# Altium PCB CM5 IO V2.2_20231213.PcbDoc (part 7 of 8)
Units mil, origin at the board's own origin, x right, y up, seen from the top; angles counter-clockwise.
Board outline 6299.61 x 3544.09 mil, 4 copper layers (Top, GND, Power, Bottom), stack 35.4 mil thick; 482 components, 404 nets, 1857 pads, 2731 vias.
Unrouted connection lines stored in the file: 1872.
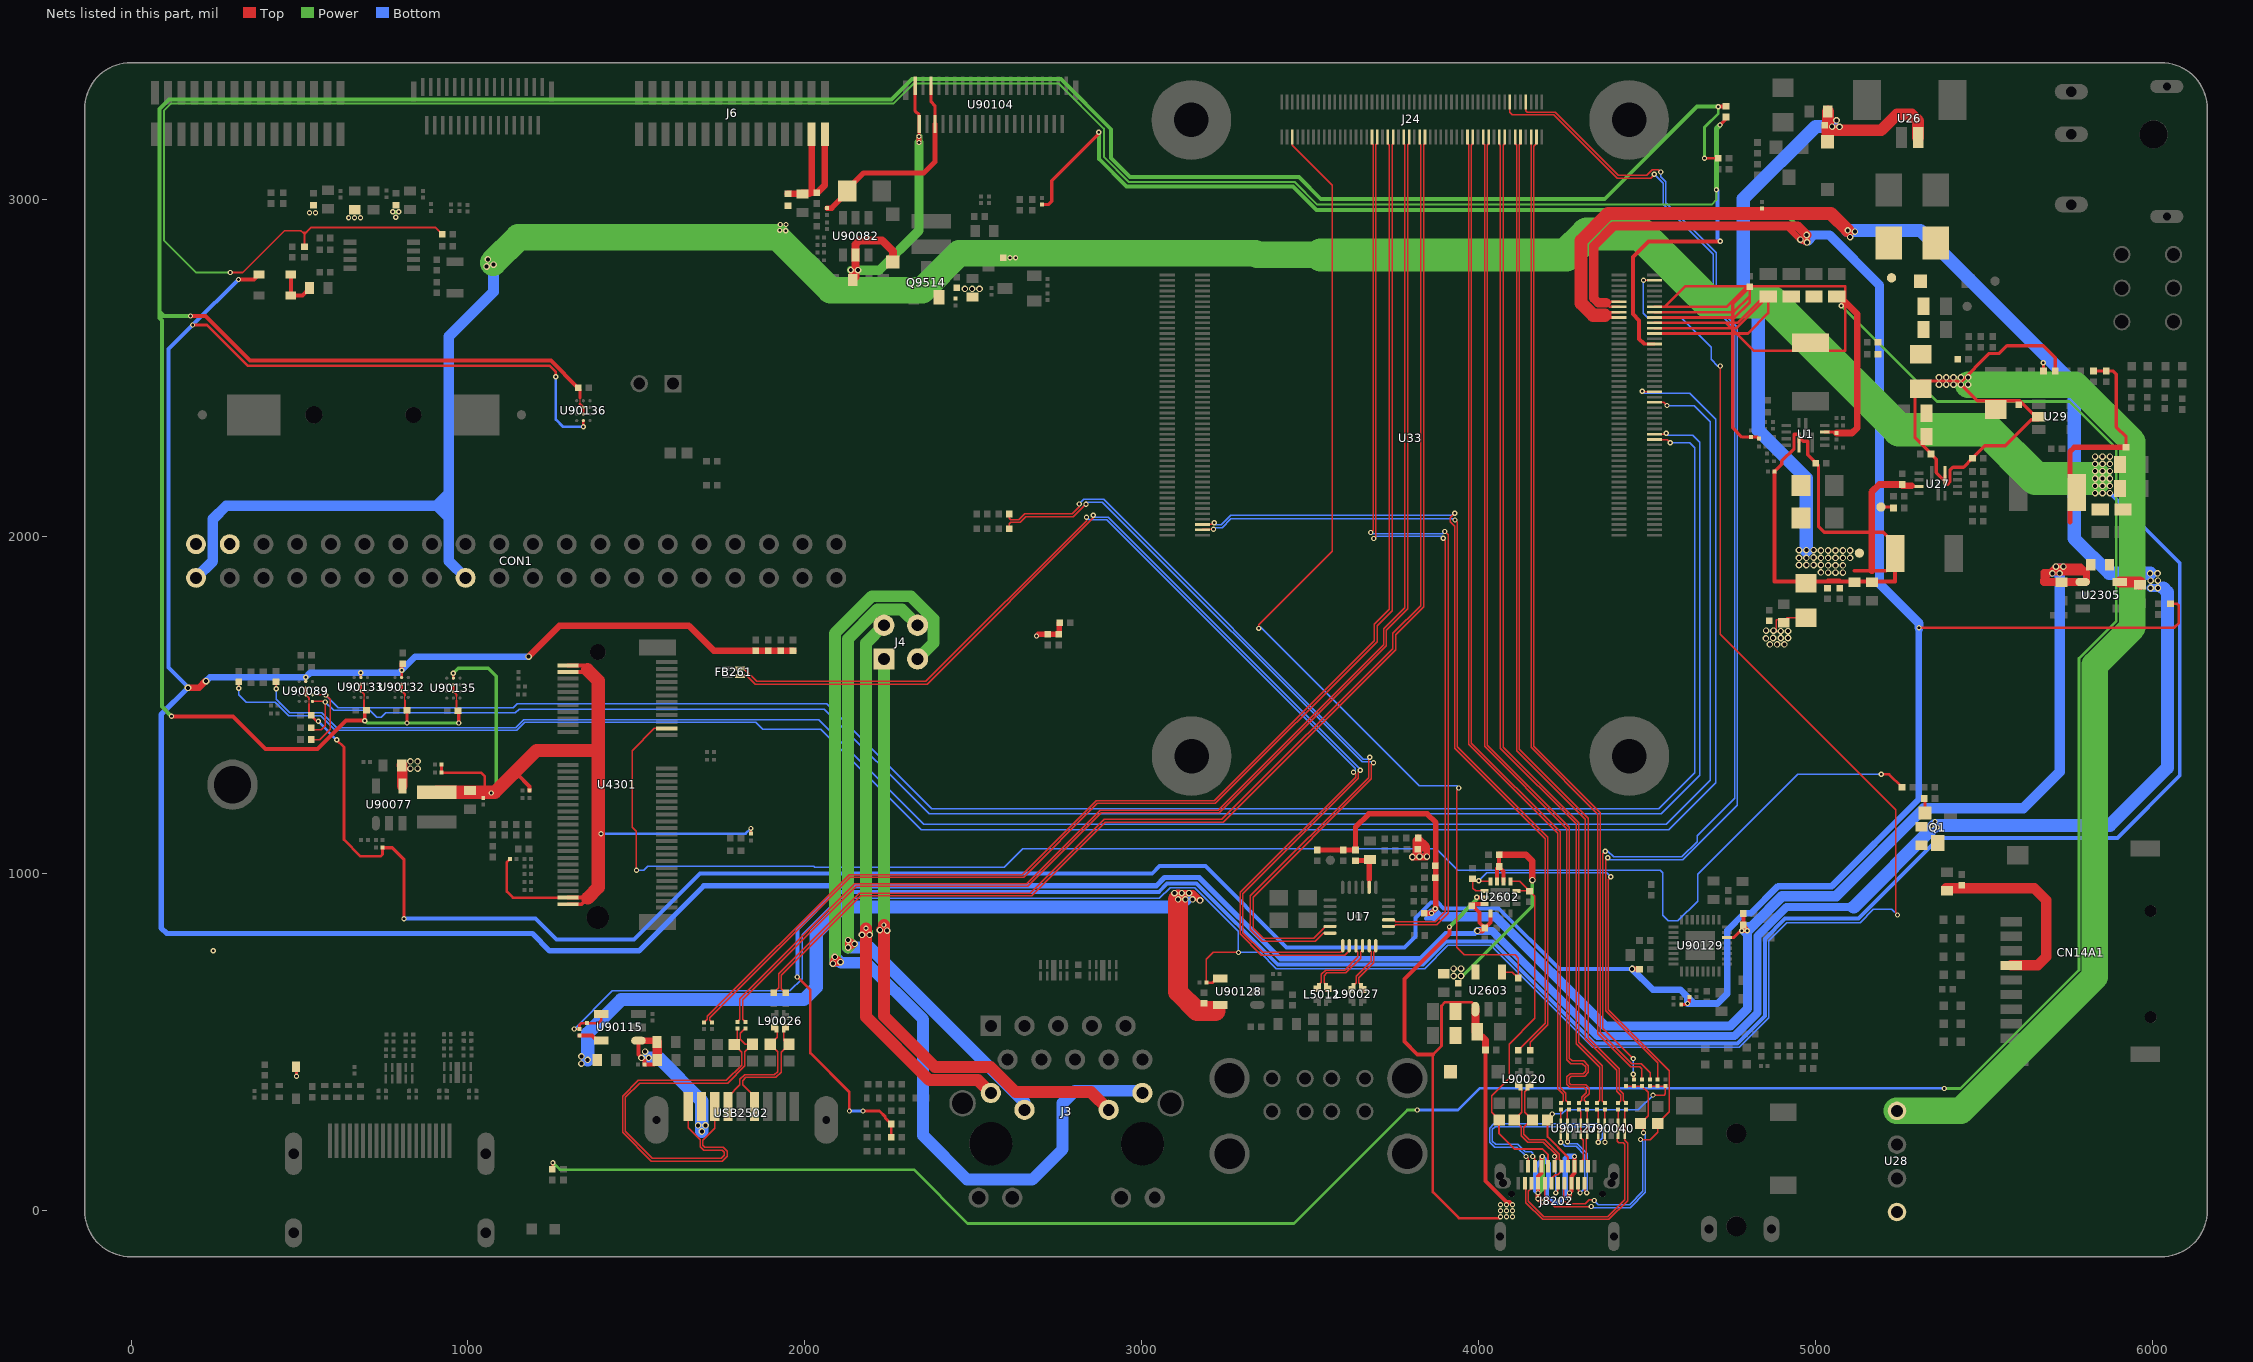
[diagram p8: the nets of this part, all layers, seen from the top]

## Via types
v1: diameter 15.75, hole 7.87, Top to Bottom, 2292 vias
v2: diameter 19.68, hole 11.81, Top to Bottom, 439 vias

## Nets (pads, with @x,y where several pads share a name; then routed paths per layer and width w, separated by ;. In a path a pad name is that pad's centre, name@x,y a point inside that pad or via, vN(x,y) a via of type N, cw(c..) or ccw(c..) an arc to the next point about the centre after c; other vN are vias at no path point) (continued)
SSTX_1N: C2280.2 D90035.1 USB2502.8 | length 1196.5
  Top w3.94: USB2502.8@1732.35,307.18 1732.35,243.11 1696.85,207.61 1696.85,191.93 1702.76,186.02 1757.87,186.02 1768.7,175.2 1768.7,159.45 1754.92,145.67 1544.23,145.67 1458.66,231.24 1458.66,337.66 1505.85,384.84 1766.99,384.84 1812.91,430.76 1812.91,468.98 D90035.1@1790.35,491.54 1790.35,496.06 1799.21,504.92 C2280.2@1799.21,539.37
SSTX_1P: C2281.2 D90037.1 USB2502.9 | length 1200.7
  Top w3.94: USB2502.9@1653.61,307.18 1653.61,244.03 1688.98,208.66 1688.98,188.67 1699.49,178.15 1754.61,178.15 1760.83,171.94 1760.83,162.71 1751.66,153.54 1547.49,153.54 1466.54,234.5 1466.54,334.39 1509.11,376.97 1770.25,376.97 1821.85,428.57 1821.85,469.88 D90037.1@1844.49,492.52 1823.43,492.52 1808.07,507.87 1808.07,524.61 C2281.2@1822.83,539.37
TP_INT_L: R95596.1 U33.37 U90089.C3 | length 5564.3
  Top w3.94: R95596.1@534.45,1396.65 560.04,1396.65 590.55,1427.17 590.55,1515.75 v1(577.76,1528.54) 576.77,1529.53 U90089.C3@538.39,1529.53 ; U33.37@4520.47,2286.81 4558.66,2286.81 v1(4567.91,2277.56)
  Bottom w3.94: v1(577.76,1528.54) 615.16,1491.14 1133.86,1491.14 1145.67,1502.95 2064.96,1502.95 2375.98,1191.93 4533.46,1191.93 4639.76,1298.23 4639.76,2262.8 4625,2277.56 v1(4567.91,2277.56)
TP_RST_L: R95597.1 U33.39 U90089.D3 | length 5584.4
  Top w3.94: R95597.1@534.45,1432.09 534.45,1425.2 563.98,1425.2 576.77,1437.99 v1(576.77,1507.87) 576.77,1509.84 U90089.D3@538.39,1509.84 ; U33.39@4520.47,2302.56 4553.54,2302.56 v1(4556.1,2305.12)
  Bottom w3.94: v1(576.77,1507.87) 601.38,1483.27 708.66,1483.27 729.33,1462.6 743.11,1462.6 755.91,1475.39 1140.38,1475.39 1152.19,1487.2 2057.09,1487.2 2368.11,1176.18 4541.34,1176.18 4655.51,1290.35 4655.51,2279.53 4634.84,2300.2 4561.02,2300.2 v1(4556.1,2305.12)
TR0: J3.11 J4.2 | length 1785.8
  Top w19.68: v2(2169.29,816.93) v1(2181.1,836.61) v2(2191.93,816.93) v2(2169.29,816.93)
  Top w35.43: v1(2181.1,836.61) 2181.1,573.82 2369.09,385.83 2513.36,385.83 J3.11@2551.39,347.8
  Power w19.68: v2(2169.29,816.93) v2(2191.93,816.93) 2191.93,825.79 v1(2181.1,836.61) v2(2169.29,816.93)
  Power w35.43: v1(2181.1,836.61) 2181.1,849.38 ; 2181.13,849.41 2181.13,1682.66 J4.2@2234.28,1735.81
TR1: J3.12 J4.1 | length 2078.4
  Top w19.68: v2(2127.95,779.53) v2(2147.64,790.35) v2(2127.95,801.18) v2(2127.95,779.53)
  Power w19.68: v2(2127.95,779.53) 2134.22,776.93 v2(2147.64,790.35) 2127.95,810.04 v2(2127.95,801.18)
  Power w35.43: v2(2127.95,779.53) v2(2127.95,801.18) ; v2@2127.95,810.04 2127.95,1695.46 2214.97,1782.48 2287.61,1782.48 J4.1@2334.28,1735.81
  Bottom w19.68: v2(2127.95,779.53) v2(2127.95,801.18) v2(2147.64,790.35)
  Bottom w35.43: v2(2127.95,779.53) 2192.71,779.53 2651.39,320.84 J3.12@2651.39,297.8
TR2: J3.13 J4.4 | length 1942.8
  Top w19.68: v2(2222.44,830.71) 2222.44,834.65 v1(2234.25,846.46) v2(2244.09,829.72)
  Top w35.43: v1(2234.25,846.46) 2234.25,576.35 2385.4,425.2 2550.15,425.2 2624.96,350.39 2848.79,350.39 J3.13@2901.39,297.8
  Power w19.68: v2(2222.44,830.71) v1(2234.25,846.46) v2(2244.09,829.72) v2(2222.44,830.71)
  Power w35.43: v1(2234.25,846.46) J4.4@2234.28,1635.81
TR3: J3.14 J4.3 | length 3231.5
  Top w19.68: v2(2082.68,731.3) v2(2088.58,751.97) v2(2105.31,736.22) v2(2082.68,731.3)
  Power w19.68: v2(2082.68,731.3) 2082.68,751.97 v2(2088.58,751.97) v2(2105.31,736.22) v2(2082.68,731.3)
  Power w35.43: v2(2088.58,751.97) 2088.58,1711.77 2198.66,1821.85 2314.22,1821.85 2380.93,1755.13 2380.93,1682.46 J4.3@2334.28,1635.81
  Bottom w19.68: v2(2088.58,751.97) 2082.68,746.06 v2(2082.68,731.3) v2(2105.31,736.22)
  Bottom w35.43: v2(2088.58,751.97) 2106.3,734.25 2182.31,734.25 2350.39,566.16 2350.39,221.46 2481.3,90.55 2674.21,90.55 2764.76,181.1 2764.76,317.91 2801.18,354.33 2994.86,354.33 J3.14@3001.39,347.8
TYPEC0_CC1: C2612.1 ESD2702.1 J8202.A5 U2602.10 U2602.11 | length 1103.4
  Top w3.94: ESD2702.1@4060.04,267.32 4037.48,289.88 4037.48,339.65 4089.57,391.73 4089.57,492.07 4166.34,568.84 4166.34,931.48 4151.19,946.62 C2612.1@4150.22,946.62 ; U2602.11@4093.14,975.56 4121.29,975.56 C2612.1@4150.22,946.62 ; U2602.10@4111.25,947.61 4150.22,947.61 C2612.1@4150.22,946.62
  Top w5.91: ESD2702.1@4060.04,267.32 4060.04,227.36 4105.31,182.09 4187.55,182.09 4205.26,164.37 J8202.A5@4205.26,130.51
TYPEC0_CC2: C2613.1 ESD2701.1 J8202.B5 U2602.1 U2602.14 | length 1917.8
  Top w3.94: v1(3999.02,977.36) v1@3999.02,975.56 ; U2602.1@4015.97,947.61 3990.39,947.61 3982.28,955.71 3982.28,981.69 C2613.1@3980.93,983.04 3980.93,978.88 3984.25,975.56 v1@3999.02,975.56 ; U2602.14@4034.08,975.56 v1@3999.02,975.56 ; J8202.B5@4254.92,79.33 J8202.B5@4254.48,79.33 4250.98,75.84 4250.98,28.1 4260.38,18.7 4314.96,18.7 4326.77,30.51 4335.63,30.51 v1(4342.52,28.54) ; v1(4390.75,989.17) 4391.66,988.26 4383.86,980.45 4383.86,595.47 4564.96,414.37 4564.96,291.93 ESD2701.1@4530.51,257.48 4530.51,231.3 4508.86,209.65 v1(4479.33,209.65)
  Bottom w3.94: v1(3999.02,977.36) 4022.64,1000.98 4378.94,1000.98 v1(4390.75,989.17) ; v1(4342.52,28.54) 4354.33,16.73 4446.85,16.73 4486.22,56.1 4486.22,202.76 v1(4479.33,209.65)
TYPEC0_OTG_DM: R91188.1 U33.103 | length 2475.8
  Top w3.94: U33.103@3179.13,2019.09 3179.13,2020.3 v1(3212.38,2020.3) ; v1(3929.13,2048.23) 3936.02,2041.34 3936.02,1375 4204.92,1106.1 4204.92,550.2 4152.56,497.83 R91188.1@4152.56,474.41
  Bottom w3.94: v1(3212.38,2020.3) 3217.67,2025.59 3237.65,2025.59 3264.22,2052.17 3925.2,2052.17 v1(3929.13,2048.23)
TYPEC0_OTG_DP: R91189.1 U33.105 | length 2517.3
  Top w3.94: U33.105@3179.13,2034.84 3208.65,2034.84 3214.56,2040.75 v1(3214.56,2039.95) ; v1(3928.15,2067.91) 3915.35,2055.12 3915.35,2042.32 3928.15,2029.53 3928.15,1371.06 4197.05,1102.17 4197.05,554.33 R91189.1@4117.13,474.41
  Bottom w3.94: v1(3214.56,2039.95) 3220.45,2034.05 3234.97,2034.05 3262.93,2062.01 3922.24,2062.01 v1(3928.15,2067.91)
TYPEC0_SBU1: C2010.1 J24.3 | length 2959.2
  Top w3.94: J24.3@4170.67,3184.65 4170.67,3165.35 4162.8,3157.48 4162.8,1376.97 4360.24,1179.53 4360.24,527.56 4453.74,434.06 4481.3,434.06 4507.87,407.48 C2010.1@4507.87,387.8
TYPEC0_SBU1_DC: J24.8 R2004.1 | length 3668.1
  Top w3.94: J24.8@4139.17,3288.58 4139.17,3262.8 4143.11,3258.86 4226.38,3258.86 4413.39,3071.85 4498.03,3071.85 4513.78,3087.6 4532.48,3087.6 v1(4539.37,3080.71) ; v1(4381.89,1046.26) 4381.4,1046.75 4375.98,1041.34 4375.98,591.54 4530.51,437.01 R2004.1@4530.51,387.8
  Bottom w3.94: v1(4381.89,1046.26) 4382.38,1046.75 4388.78,1040.35 4605.43,1040.35 4766.73,1201.66 4766.73,2620.08 4703.74,2683.07 4703.74,2840.55 4555.12,2989.17 4555.12,3051.18 4539.37,3066.93 v1(4539.37,3080.71)
TYPEC0_SBU2: C2011.1 J24.5 | length 2949
  Top w3.94: J24.5@4154.92,3184.65 4154.92,1373.03 4352.36,1175.59 4352.36,523.62 4449.8,426.18 4477.36,426.18 4483.27,420.28 C2011.1@4483.27,387.8
TYPEC0_SBU2_DC: J24.14 R2007.1 | length 3685.5
  Top w3.94: J24.14@4091.93,3288.58 4091.93,3258.46 4099.41,3250.98 4222.44,3250.98 4410.43,3062.99 4509.84,3062.99 v1(4520.67,3073.82) ; v1(4375,1064.96) 4368.11,1058.07 4368.11,539.37 v1(4457.68,449.8) ; v1(4457.68,403.54) 4459.65,401.57 R2007.1@4459.65,387.8
  Bottom w3.94: v1(4375,1064.96) 4382.87,1064.96 4399.61,1048.23 4602.16,1048.23 4647.64,1093.7 4647.64,1111.65 4758.86,1222.87 4758.86,2616.14 4695.87,2679.13 4695.87,2836.61 4547.24,2985.24 4547.24,3047.24 v1(4520.67,3073.82) ; v1(4457.68,403.54) v1(4457.68,449.8)
TYPEC0_SSRX1N: J24.11 R2013.1 | length 2999.3
  Top w3.94: J24.11@4107.68,3184.65 4107.68,3165.35 4112.2,3160.83 4112.2,1363.19 4315.94,1159.45 4315.94,508.19 4408.46,415.67 4408.46,353.35 4420.28,341.54 4420.28,325.4 R2013.1@4412.79,317.91
TYPEC0_SSRX1P: J24.9 R2015.1 | length 3000
  Top w3.94: J24.9@4123.43,3184.65 4124.02,3184.65 4124.02,3165.35 4120.08,3161.42 4120.08,1367.13 4323.82,1163.39 4323.82,511.45 4416.34,418.93 4416.34,357.28 4428.15,345.47 4428.15,326.17 R2015.1@4436.41,317.91
TYPEC0_SSRX2N: J24.23 R2016.1 | length 3117.9
  Top w3.94: J24.23@4013.19,3184.65 4012.8,3184.65 4012.8,3165.35 4016.73,3161.42 4016.73,1376.38 4260.83,1132.28 4260.83,446.85 4272.64,435.04 4307.09,435.04 4316.93,425.2 4316.93,412.4 4310.04,405.51 4270.67,405.51 4260.83,395.67 4260.83,373.17 4269.83,364.17 4312.99,364.17 4318.9,358.27 4318.9,348.43 4305.12,334.65 4305.12,325.77 R2016.1@4297.25,317.9
TYPEC0_SSRX2P: J24.21 R2017.1 | length 3117.3
  Top w3.94: J24.21@4028.94,3184.65 4028.94,3164.37 4024.61,3160.04 4024.61,1380.31 4268.7,1136.22 4268.7,450.79 4276.57,442.91 4310.35,442.91 4324.8,428.46 4324.8,409.14 4313.3,397.64 4274.61,397.64 4268.7,391.73 4268.7,376.43 4273.09,372.05 4316.93,372.05 4326.77,362.2 4326.77,345.16 4312.99,331.38 4312.99,325.78 R2017.1@4320.87,317.9
TYPEC0_SSTX1N: C2013.1 J24.17 | length 2994.2
  Top w3.94: J24.17@4060.43,3184.65 4060.04,3184.65 4060.04,3164.37 4063.98,3160.43 4063.98,1370.47 4288.39,1146.06 4288.39,494.09 4358.27,424.21 4358.27,326.38 C2013.1@4349.79,317.91
TYPEC0_SSTX1P: C2014.1 J24.15 | length 2993.4
  Top w3.94: J24.15@4076.18,3184.65 4076.18,3164.37 4071.85,3160.04 4071.85,1374.41 4296.26,1150 4296.26,498.03 4366.14,428.15 4366.14,325.18 C2014.1@4373.42,317.91
TYPEC0_SSTX2N: C2019.1 J24.29 | length 2987.8
  Top w3.94: J24.29@3965.94,3184.65 3965.55,3184.65 3965.55,3165.35 3969.49,3161.42 3969.49,1382.28 4233.27,1118.5 4233.27,360.24 4250,343.5 4250,324.78 C2019.1@4243.12,317.9
TYPEC0_SSTX2P: C2020.1 J24.27 | length 2988.4
  Top w3.94: J24.27@3981.69,3184.65 3981.69,3164.37 3977.36,3160.04 3977.36,1386.22 4241.14,1122.44 4241.14,364.17 4257.87,347.44 4257.87,326.76 C2020.1@4266.74,317.9
TYPEC5V_PWREN_H: J24.95 R2611.1 U2603.4 | length 3178.5
  Top w3.94: v1(3346.46,1726.38) 3346.46,1737.2 3564.96,1955.71 3564.96,3042.04 3446.26,3160.74 J24.95@3446.26,3184.65 ; v1(3939.96,1252.95) 3933.8,1246.79 3933.8,780.57 3956.63,757.74 4107.33,757.74 4117.13,747.94 R2611.1@4117.13,688.98 4099.41,706.69 U2603.4@4067.91,706.69
  Bottom w3.94: v1(3346.46,1726.38) 3350.89,1730.81 3822.83,1258.86 3934.06,1258.86 v1(3939.96,1252.95)
TYPEC_SBU1: C2010.2 ESD2703.1 J8202.A8 R2004.2 R2005.1 | length 616.9
  Top w3.94: ESD2703.1@4203.74,267.32 4203.74,269.05 4202.01,269.05 4217.95,285 v1(4217.52,285.43) ; C2010.2@4507.87,368.11 R2004.2@4530.51,368.11 R2005.1@4553.15,368.11 4553.15,345.47 4549.21,341.54 v1(4516.73,341.54)
  Top w5.91: ESD2703.1@4203.74,267.32 4203.74,217.52 4264.32,156.94 J8202.A8@4264.32,130.51
  Bottom w3.94: v1(4217.52,285.43) 4246.06,285.43 4258.86,298.23 4473.43,298.23 v1(4516.73,341.54)
TYPEC_SBU2: C2011.2 ESD2704.1 J8202.B8 R2006.1 R2007.2 | length 760.7
  Top w3.94: J8202.B8@4195.42,79.33 4194.88,79.33 4194.88,40.35 4224.41,10.83 v1(4333.66,10.83) ; R2006.1@4437.01,368.11 R2007.2@4459.65,368.11 C2011.2@4483.27,368.11 4501.89,349.49 4501.89,280.04 ESD2704.1@4479.33,257.48 4488.19,257.48 v1(4488.19,229.33)
  Bottom w3.94: v1(4333.66,10.83) 4336.61,7.87 4449.13,7.87 4494.09,52.84 4494.09,223.43 v1(4488.19,229.33)
TYPEC_SSRX1N: J8202.B10 R2013.2 U90040.4 U90040.7 | length 675.2
  Top w3.94: J8202.B10@4156.05,79.33 4156.05,65.5 4146.65,56.1 4146.65,25.9 4192.24,-19.69 4381.89,-19.69 4433.07,31.5 4433.07,194.88 4428.15,199.8 4415.35,199.8 4410.43,204.72 4410.43,212.6 4412.78,214.95 U90040.4@4412.78,224.9 ; U90040.4@4412.78,218.12 U90040.4@4412.78,224.9 ; R2013.2@4412.79,298.22 4412.79,282.48 U90040.7@4412.78,259.34 U90040.4@4412.78,224.9
TYPEC_SSRX1P: J8202.B11 R2015.2 U90040.5 U90040.6 | length 679.3
  Top w3.94: J8202.B11@4136.36,79.33 4136.36,66.39 4138.78,63.98 4138.78,22.64 4188.98,-27.56 4385.83,-27.56 4440.94,27.56 4440.94,198.82 4432.47,207.29 U90040.5@4432.47,224.9 U90040.6@4432.47,259.34 4432.47,294.29 R2015.2@4436.41,298.22
TYPEC_SSRX2N: J8202.A10 R2016.2 U90127.4 U90127.7 | length 175.6
  Top w3.94: R2016.2@4297.25,298.21 4302.17,293.3 U90127.7@4302.17,259.33 U90127.4@4302.17,224.89 4302.17,215.55 4310.04,207.68 4310.04,151.57 4303.69,145.22 J8202.A10@4303.69,130.51
TYPEC_SSRX2P: J8202.A11 R2017.2 U90127.5 U90127.6 | length 172
  Top w3.94: R2017.2@4320.87,298.21 4321.86,297.23 U90127.6@4321.86,259.33 U90127.5@4321.86,224.89 4321.86,214.57 4317.91,210.62 4317.91,151.57 4323.37,146.12 J8202.A11@4323.37,130.51
TYPEC_SSTX1N: C2013.2 J8202.A3 U90040.1 U90040.10 | length 681.5
  Top w3.94: v1(4159.45,159.45) 4165.35,153.54 4165.35,130.51 J8202.A3@4165.89,130.51 ; C2013.2@4349.79,298.22 4353.73,294.29 U90040.10@4353.73,259.34 U90040.1@4353.73,224.9 4354.33,224.9 v1(4354.33,201.77)
  Bottom w3.94: v1(4159.45,159.45) 4159.45,168.4 4154.62,173.23 4137.12,173.23 4115.47,194.88 4050.2,194.88 4040.05,205.03 4040.05,239.85 4048.23,248.03 4352.36,248.03 4366.14,234.25 4366.14,213.58 v1(4354.33,201.77)
TYPEC_SSTX1P: C2014.2 J8202.A2 U90040.2 U90040.9 | length 687.7
  Top w3.94: v1(4139.76,159.45) 4145.67,153.54 4145.67,130.51 J8202.A2@4146.21,130.51 ; C2014.2@4373.42,298.22 4373.42,282.48 U90040.9@4373.42,259.34 U90040.2@4373.42,224.9 4374.02,224.9 v1(4374.02,201.77)
  Bottom w3.94: v1(4139.76,159.45) 4112.2,187.01 4046.26,187.01 4031.5,201.77 4031.5,243.11 4044.29,255.91 4356.3,255.91 4374.02,238.19 v1(4374.02,201.77)
TYPEC_SSTX2N: C2019.2 J8202.B3 U90127.1 U90127.10 | length 332.2
  Top w3.94: v1(4243.11,201.77) U90127.1@4243.12,224.89 U90127.10@4243.12,259.33 C2019.2@4243.12,298.21 ; J8202.B3@4293.85,79.33 4294.29,79.33 4294.29,57.09 v1(4300.2,51.18)
  Bottom w3.94: v1(4243.11,201.77) 4255.91,188.98 4288.39,188.98 4313.98,163.39 4313.98,64.96 v1(4300.2,51.18)
TYPEC_SSTX2P: C2020.2 J8202.B2 U90127.2 U90127.9 | length 318.8
  Top w3.94: v1(4262.8,202.76) U90127.2@4262.81,224.89 U90127.9@4262.81,259.33 4262.81,294.28 C2020.2@4266.74,298.21 ; J8202.B2@4313.53,79.33 4313.98,79.33 4313.98,57.09 v1(4319.88,51.18)
  Bottom w3.94: v1(4262.8,202.76) 4268.7,196.85 4292.32,196.85 4321.85,167.32 4321.85,53.15 v1(4319.88,51.18)
UART2_RX_M0: R168.2 U33.51 | length 5790.9
  Top w3.94: R168.2@430.12,1567.91 431.1,1567.91 v1(431.1,1547.24) ; U33.51@4520.47,2397.05 4548.82,2397.05 v1(4558.07,2387.8)
  Bottom w3.94: v1(431.1,1547.24) 431.1,1515.75 471.46,1475.39 566.62,1475.39 609.93,1432.09 1141.62,1432.09 1165.24,1455.71 2041.34,1455.71 2352.36,1144.68 4556.16,1144.68 4687.01,1275.53 4687.01,2339.57 4638.78,2387.8 v1(4558.07,2387.8)
UART2_TX_M0: R167.2 U33.55 | length 6033.8
  Top w3.94: v1(319.88,1549.21) R167.2@319.88,1567.91 ; v1(4484.25,2430.12) 4484.25,2428.54 U33.55@4520.47,2428.54
  Bottom w3.94: v1(319.88,1549.21) 319.88,1529.53 342.52,1506.89 428.15,1506.89 467.52,1467.52 563.36,1467.52 606.67,1424.21 1144.88,1424.21 1168.5,1447.83 1853.35,1447.83 1874.02,1427.17 2046.26,1427.17 2344.49,1128.94 4562.68,1128.94 4702.76,1269.01 4702.76,2347.44 4625.98,2424.21 4490.16,2424.21 v1(4484.25,2430.12)
USB1_DM: L90027.2 R249.2 U17.11 | length 156.9
  Top w3.94: R249.2@3622.39,654.78 3622.63,654.78 3622.63,654.53 3628.29,660.19 L90027.2@3628.29,663.64 3628.29,667.32 3635.83,674.86 3635.83,693.9 3680.12,738.19 3680.12,766.73 3674.4,772.45 U17.11@3674.4,784.74
USB1_DP: L90027.1 R250.2 U17.12 | length 156.5
  Top w3.94: R250.2@3655.85,654.78 3655.61,654.78 3655.61,654.53 3649.95,660.19 L90027.1@3649.95,663.64 3649.95,669.29 3643.7,675.54 3643.7,689.96 3687.99,734.25 3687.99,765.75 3694.09,771.84 U17.12@3694.09,784.74
USB2_DM: L5012.4 R253.1 U17.9 | length 215.5
  Top w3.94: R253.1@3519,656.68 3519.74,656.68 3519.74,655.94 3524.91,661.11 L5012.4@3524.91,663.57 3524.91,668.31 3532.48,675.88 3532.48,699.5 3545.58,712.6 3601.38,712.6 3640.75,751.97 3640.75,765.75 3635.03,771.46 U17.9@3635.03,784.74
USB2_DP: L5012.3 R254.1 U17.10 | length 215.4
  Top w3.94: R254.1@3552.47,656.68 3551.73,656.68 3551.73,655.94 3546.56,661.11 L5012.3@3546.56,663.57 3546.56,668.31 3540.35,674.51 3540.35,696.24 3548.84,704.72 3605.31,704.72 3648.62,748.03 3648.62,766.73 3654.72,772.83 U17.10@3654.72,784.74
USB3_DM: FB261.1 R95142.2 U17.7 | length 3357.2
  Top w3.94: FB261.1@1812.01,1585.63 1827.76,1585.63 1852.36,1561.02 2362.2,1561.02 2855.31,2054.13 v1(2855.31,2062.01) ; U17.7@3595.66,784.74 3595.66,769.87 3590.55,764.76 3358.27,764.76 3299.21,823.82 3299.21,938.98 3641.73,1281.5 3641.73,1299.21 v1(3647.64,1305.12)
  Top w7.87: R95142.2@1798.72,1585.14 1812.01,1585.14 FB261.1@1812.01,1585.63
  Bottom w3.94: v1(2855.31,2062.01) 2855.31,2056.1 2899.61,2056.1 3650.18,1305.53 v1(3647.64,1305.12)
USB3_DP: FB261.2 R95141.2 U17.8 | length 3377.4
  Top w3.94: FB261.2@1812.01,1607.28 1817.91,1607.28 1856.3,1568.9 2358.27,1568.9 2835.63,2046.26 v1(2835.63,2056.1) ; U17.8@3615.35,784.74 3615.35,769.98 3602.26,756.89 3354.33,756.89 3291.34,819.88 3291.34,942.91 3633.86,1285.43 3633.86,1293.31 v1(3627.95,1299.21)
  Top w7.87: R95141.2@1798.72,1607.78 1812.01,1607.78 FB261.2@1812.01,1607.28
  Bottom w3.94: v1(2835.63,2056.1) 2843.5,2048.23 2895.67,2048.23 3632.87,1311.02 3632.87,1299.21 v1(3627.95,1299.21)
USB4_DM: R95611.2 U17.5 | length 2342
  Top w3.94: R95611.2@2606.3,2022.64 2606.3,2037.4 2610.24,2041.34 2638.17,2041.34 2654.71,2057.87 2796.46,2057.87 v1(2833.86,2095.28) ; U17.5@3558.26,841.83 3546.06,841.83 3510.53,806.3 3360.35,806.3 3329.72,836.92 3329.72,929.18 3681.1,1280.56 3681.1,1322.05 v1(3687.01,1327.95)
  Bottom w3.94: v1(2833.86,2095.28) 2833.86,2101.18 2882.68,2101.18 3653.54,1330.31 3687.01,1330.31 v1(3687.01,1327.95)
USB4_DP: R95610.1 U17.6 | length 2354.2
  Top w3.94: R95610.1@2606.3,2065.94 2606.3,2053.15 2610.24,2049.21 2634.84,2049.21 2651.57,2065.94 2793.11,2065.94 2814.17,2087.01 v1(2814.17,2095.67) ; U17.6@3558.26,822.14 3537.89,822.14 3514.17,798.43 3357.09,798.43 3321.85,833.66 3321.85,932.44 3673.23,1283.82 3673.23,1341.73 v1(3675.98,1344.49)
  Bottom w3.94: v1(2814.17,2095.67) 2827.56,2109.06 2886.17,2109.06 3657.03,1338.19 3669.69,1338.19 v1(3675.98,1344.49)
USB20_HOST0_DM: J24.65 U17.14 | length 2739.4
  Top w3.94: v1(3679.13,2010.83) 3686.02,2017.72 3686.02,3161.42 3682.09,3165.35 3682.09,3184.65 J24.65@3682.48,3184.65 ; U17.14@3731.49,841.83 3747.05,841.83 3752.66,847.44 3874.71,847.44 3908.46,881.2 3908.46,2003.94 v1(3898.62,2013.78)
  Bottom w3.94: v1(3679.13,2010.83) 3676.18,2010.83 3676.18,2007.87 3892.72,2007.87 v1(3898.62,2013.78)
USB20_HOST0_DP: J24.63 U17.15 | length 2702.6
  Top w3.94: v1(3687.99,1993.11) 3693.9,1999.02 3693.9,3162.4 3698.23,3166.73 J24.63@3698.23,3184.65 ; U17.15@3731.49,861.51 3747.05,861.51 3753.25,855.31 3870.77,855.31 3900.59,885.14 3900.59,1987.2 v1(3893.7,1994.09)
  Bottom w3.94: v1(3687.99,1993.11) 3694.88,2000 3887.8,2000 v1(3893.7,1994.09)
USB20_HOST1_DM: J24.47 R95552.1 | length 3839.7
  Top w3.94: R95552.1@1907.48,644.68 1922.24,659.45 1922.24,701.77 2161.42,940.94 2669.25,940.94 2887.77,1159.47 3237.48,1159.47 3744.76,1666.75 3744.76,1711.3 3827.76,1794.29 3827.76,3162.4 3823.82,3166.34 3823.82,3184.65 J24.47@3824.21,3184.65
USB20_HOST1_DP: J24.45 R95551.1 | length 3838.3
  Top w3.94: R95551.1@1942.91,644.68 1930.12,657.48 1930.12,697.83 2165.35,933.07 2672.59,933.07 2891.09,1151.57 3240.72,1151.57 3752.64,1663.49 3752.64,1707.36 3835.63,1790.35 3835.63,3161.42 3839.96,3165.75 J24.45@3839.96,3184.65
USB30_2_SSRXN: J24.59 R91181.1 | length 3978.6
  Top w3.94: R91181.1@1700.79,557.09 1709.65,565.94 1709.65,574.8 2130.91,996.06 2645.24,996.06 2863.94,1214.77 3214.83,1214.77 3689.64,1689.58 3689.64,1738.86 3734.25,1783.46 3734.25,3160.43 3729.72,3164.96 J24.59@3729.72,3184.65
USB30_2_SSRXP: J24.57 R91182.1 | length 3977.6
  Top w3.94: R91182.1@1724.48,557.18 1717.52,564.13 1717.52,570.87 2134.84,988.19 2648.54,988.19 2867.24,1206.89 3218.09,1206.89 3697.52,1686.32 3697.52,1734.92 3742.13,1779.53 3742.13,3161.42 3746.06,3165.35 3746.06,3184.65 J24.57@3745.47,3184.65
USB30_2_SSTXN: C2280.1 J24.53 | length 3952
  Top w3.94: C2280.1@1799.21,559.06 1807.09,566.93 1807.09,627.95 2147.64,968.5 2657.71,968.5 2876.38,1187.17 3226.21,1187.17 3717.2,1678.17 3717.2,1725.08 3780.51,1788.39 3780.51,3161.42 3776.57,3165.35 3776.57,3184.65 J24.53@3776.97,3184.65
USB30_2_SSTXP: C2281.1 J24.51 | length 3951.4
  Top w3.94: C2281.1@1822.83,559.06 1814.96,566.93 1814.96,624.02 2151.57,960.63 2660.98,960.63 2879.63,1179.28 3229.46,1179.28 3725.08,1674.91 3725.08,1721.14 3788.39,1784.45 3788.39,3161.42 3792.72,3165.75 J24.51@3792.72,3184.65
USB_HOST_PWREN_H: R91375.2 R95555.1 R95579.1 U33.97 U90115.4 U90128.4 | length 7403.6
  Top w3.94: v1(1314.96,537.4) R91375.2@1330.71,537.4 ; R95555.1@3190.94,675.2 3190.94,744.09 3211.61,764.76 v1(3286.42,764.76) ; v1(4488.19,2759.84) 4520.47,2759.84 U33.97@4520.47,2759.25 ; v1(4716.54,2504.92) 4716.54,1708.66 5236.22,1188.98 5236.22,881.89 v1(5242.13,875.98)
  Top w7.87: R91375.2@1330.71,537.4 1330.71,549.21 1336.61,555.12 R95579.1@1353.35,555.12 1386.81,555.12 1395.67,563.98 U90115.4@1395.67,581.69 ; R95555.1@3190.94,675.2 3209.64,675.2 3214.57,680.12 3228.2,687.99 U90128.4@3232.28,687.99
  Bottom w3.94: v1(1314.96,537.4) 1428.15,650.59 1955.51,650.59 1992.13,687.21 1992.13,816.7 2100.62,925.2 3052.03,925.2 3083.52,956.69 3157.11,956.69 3286.42,827.39 v1(3286.42,764.76) 3350.42,764.76 3398.65,716.54 3839,716.54 3907.9,785.43 4035.35,785.43 4337.52,483.27 4772.16,483.27 4860.24,571.35 4860.24,799.86 4913.72,853.35 5130.88,853.35 5170.25,892.72 5225.39,892.72 v1(5242.13,875.98) ; v1(4488.19,2759.84) 4488.19,2661.42 4500.98,2648.62 4600.39,2648.62 4688.98,2560.04 4688.98,2524.61 4708.66,2504.92 v1(4716.54,2504.92)
USBC_D+: ESD2706.1 J8202.A6 J8202.B6 L90020.3 R95547.2 | length 479.4
  Top w3.94: R95547.2@4117.13,372.05 4117.86,372.05 4117.86,372.79 4123.03,367.62 L90020.3@4123.03,365.16 4127.12,361.07 4127.12,290.21 ESD2706.1@4104.57,267.65 4125,247.22 4125,221.46 4144.69,201.77 4190.94,201.77 4230.31,162.4 4230.31,151.43 4224.95,146.06 J8202.A6@4224.95,130.51 ; v1(4228.35,51.18) 4234.25,57.09 4234.25,79.33 J8202.B6@4234.79,79.33
  Bottom w3.94: v1(4224.41,159.45) 4228.35,155.51 v1(4228.35,51.18)
USBC_D-: ESD27052.1 J8202.A7 J8202.B7 L90020.4 R95546.2 | length 415.3
  Top w3.94: R95546.2@4151.57,372.05 4144.69,372.05 L90020.4@4144.69,365.16 4144.69,360.24 4136.15,351.7 4136.15,290.21 ESD27052.1@4158.7,267.65 4154.53,267.65 4132.87,246 4132.87,225.39 4148.62,209.65 4194.88,209.65 4238.19,166.34 4238.19,151.57 4244.63,145.13 J8202.A7@4244.63,130.51 4242.13,128.01 4242.13,114.17 4233.27,105.31 4226.38,105.31 4215.1,94.04 J8202.B7@4215.1,79.33
USBHP_1N: D90032.1 L90026.3 R95553.2 USB2502.2 | length 374.7
  Top w3.94: USB2502.2@1771.72,307.18 1771.72,336.71 1807.09,372.07 1807.09,387.8 1820.87,401.57 1909.37,401.57 1919.21,411.42 1919.21,469.96 D90032.1@1896.65,492.52 1917.32,513.19 1917.32,530.51 1915.35,532.48 L90026.3@1915.35,536.42 1915.35,543.31 R95553.2@1908.46,543.31
USBHP_1P: D90031.1 L90026.4 R95550.2 USB2502.3 | length 373.2
  Top w3.94: USB2502.3@1850.46,307.18 1850.46,336.71 1814.96,372.2 1814.96,383.86 1824.8,393.7 1913.39,393.7 1929.13,409.45 1929.13,468.9 D90031.1@1952.76,492.52 1948.43,492.52 1937.01,503.94 L90026.4@1937.01,536.42 1937.01,538.88 1942.18,544.05 1942.18,543.31 R95550.2@1942.91,543.31
VBUS5V0_TYPEC: C658.1 C2611.1 C90780.1 C90781.1 D41.2 J8202.A4 J8202.A9 J8202.B4 J8202.B9 U2602.2 U2603.1 | length 3047.7
  Top w7.87: U2603.1@3989.17,596.45 3989.17,606.3 3978.04,617.43 3899.91,617.43 3888.78,606.3 3888.78,487.2 3863.19,461.61 3863.19,54.13 3940.94,-23.62 4060.04,-23.62 v1(4063.98,-19.69)
  Top w11.81: 3863.19,461.61 3816.93,461.61 3778.54,500 3778.54,686.02 3912.4,819.88 v1(3912.4,840.55) ; v1(3993.11,928.15) 3993.34,927.92 U2602.2@4015.97,927.92 ; C2611.1@4019.69,475.39 4019.69,86.58 4081.66,24.61 4090.55,24.61 v1(4099.41,15.75) ; v1(4175.2,51.18) 4175.73,58.85 J8202.B9@4175.73,79.33 4175.73,100 4185.58,109.84 J8202.A4@4185.58,130.51 4185.58,157.03 v1(4187.99,159.45) ; v1(4268.7,51.18) 4274.16,56.64 J8202.B4@4274.16,79.33 4274.16,100 4284,109.84 J8202.A9@4284,130.51 4284,151.39 v1(4283.46,159.45)
  Top w15.75: v1(4175.2,51.18) v1(4175.2,33.46) v1(4189.96,23.62) ; v1(4268.7,33.46) v1(4268.7,51.18)
  Top w19.68: C90780.1@3995.08,529.53 4019.69,504.92 C2611.1@4019.69,475.39
  Top w23.62: U2603.1@3989.17,596.45 3989.17,529.53 C90780.1@3995.08,529.53
  Power w11.81: v1(3912.4,840.55) 3993.11,921.26 v1(3993.11,928.15)
  Power w15.75: v1(4175.2,51.18) 4187.99,63.98 v1(4187.99,159.45)
  Bottom w15.75: v1(4175.2,51.18) 4168.9,57.48 4168.9,129.92 4183.37,144.39 4187.99,149.03 v1(4187.99,159.45) 4191.99,152.5 4206.69,137.8 4206.69,74.8 4200.79,68.9 4200.79,39.77 4216.93,23.62 4239.76,23.62 4255.91,39.77 4255.91,152.56 4263.78,160.43 4282.48,160.43 v1(4283.46,159.45)
  other v1: 4081.69,-19.69 4099.41,-19.69 4063.98,-1.97 4081.69,-1.97 4099.41,-1.97 4063.98,15.75 4081.69,15.75
VCC3V3_SD: C4.1 C5.1 CN14A1.4 Q1.3 R220.2 | length 594.8
  Top w31.5: C4.1@5386.81,955.71 5647.64,955.71 5684.06,919.29 5684.06,751.97 5658.46,726.38 CN14A1.4@5579.5,726.38
VCC3V3_SYS: C148.1 C149.1 C150.1 C154.1 C155.1 C156.1 CON1.1 CON1.17 FB2.1 FB6.1 FB7.1 L13.2 R4.2 R10.2 R157.1 R95530.1 | length 14548.5
  Top w7.87: v1(1977.36,691.93) 2015.75,653.54 2015.75,466.09 2131.89,349.94 v1(2131.89,294.29) ; v1(2172.24,294.29) 2221.09,294.29 2238.19,277.19 2238.19,273.62 R10.2@2255.91,255.91 R4.2@2255.91,216.54
  Top w9.84: C148.1@5823.82,2490.16 R157.1@5861.22,2490.16 5882.87,2490.16 5891.73,2481.3 5891.73,2323.82 5920.28,2295.28 C150.1@5920.28,2263.78
  Top w15.75: 5753.94,2042.32 5753.94,2110.24 L13.2@5773.62,2129.92 5773.62,2158.46 5753.94,2178.15 5753.94,2250.98 5766.73,2263.78 C150.1@5920.28,2263.78
  Power w3.94: v2@1074.8,2812.01 1075.79,2811.02 v2(1075.79,2806.1)
  Power w11.81: v1@777.56,2962.6 v1(794.29,2962.6)
  Power w78.74: v2@1074.8,2812.01 1149.61,2886.81 1919.29,2886.81 2075.79,2730.31 2348.43,2730.31 2457.68,2839.57 3336.61,2839.57 3341.54,2834.65 3531.5,2834.65
  Power w98.43: 3531.5,2834.65 4258.86,2834.65 4320.87,2896.65 4480.31,2896.65 4681.1,2695.87 4867.13,2695.87 5247.05,2315.94 5506.89,2315.94 5651.57,2171.26 v2(5828.74,2171.26)
  Bottom w7.87: v1(2131.89,294.29) v1(2172.24,294.29)
  Bottom w11.81: v1(1977.36,691.93) 1977.36,834.62 2087.63,944.88 3050.23,944.88 3074.83,969.49 3162.4,969.49 3403.54,728.35 3834.11,728.35 3903.01,797.24 4040.24,797.24 4342.41,495.08 4767.26,495.08 4848.43,576.24 4848.43,804.76 4908.83,865.16 5125.98,865.16 5365.16,1104.33 5894.69,1104.33 6079.72,1289.37 6079.72,1920.28 v2(5872.05,2127.95)
  Bottom w31.5: CON1.1@192.94,1876.36 243.11,1926.53 243.11,2051.18 282.48,2090.55 905.51,2090.55 ; CON1.17@992.94,1876.36 942.91,1926.39 942.91,2055.45 ; v2(1075.79,2806.1) 1075.79,2725.39 942.91,2592.52 942.91,2127.95 ; 905.51,2090.55 907.81,2090.55 ; 905.51,2090.55 942.91,2127.95 ; 907.81,2090.55 942.91,2055.45 ; 907.81,2090.55 942.91,2090.55 ; 942.91,2055.45 942.91,2090.55 ; 942.91,2090.55 942.91,2127.95
  other v1: 2608.27,2826.77 2625,2826.77 1942.91,2906.5 1925.2,2907.48 1926.18,2925.2 1943.9,2925.2 785.43,2946.85 529.53,2959.65 547.24,2959.65 776.57,2962.6
  other v2: 5828.74,2127.95 5850.39,2127.95 5828.74,2149.61 5850.39,2149.61 5872.05,2149.61 5850.39,2171.26 5872.05,2171.26 5828.74,2192.91 5850.39,2192.91 5872.05,2192.91 5828.74,2214.57 5850.39,2214.57 5872.05,2214.57 5828.74,2236.22 5850.39,2236.22 5872.05,2236.22 1055.12,2800.2 1059.06,2821.85
VCC3V3_WF: C266.1 C267.1 C268.1 L5011.2 R95151.2 R95153.2 R95154.2 R95281.1 U4301.2 U4301.4 U4301.72 U4301.74 U90135.A2 | length 3074.9
  Top w3.94: 1386.81,1116.14 1394.69,1116.14 v1(1394.69,1117.13)
  Top w7.87: R95281.1@921.26,1321.85 C266.1@921.26,1298.23 1038.39,1298.23 1050.2,1286.42 1050.2,1240.28 ; U90135.A2@956.7,1578.74 v1(956.69,1593.5) ; R95154.2@1124.96,1042.31 1115.16,1032.51 1115.16,945.87 1133.51,927.52 U4301.72@1296.47,927.52 ; R95151.2@1839.57,1117.13 v1(1839.57,1132.87)
  Top w9.84: C267.1@1003.94,1240.28 1003.94,1245.08 C267.1@1005.91,1245.08 ; C268.1@1045.28,1223.43 1045.28,1235.36 1050.2,1240.28 ; v1@1066.81,1240.28 v1(1068.9,1238.19)
  Top w11.81: 1134.84,1295.28 1144.63,1295.28 1182.05,1257.86 R95153.2@1182.05,1246.05 ; U4301.74@1296.47,907.83 1336.97,907.83 1355.31,926.18 1355.31,927.52 U4301.72@1296.47,927.52 ; U4301.4@1296.47,1596.81 1347.79,1596.81 1354.33,1603.35 1354.33,1616.5 U4301.2@1296.47,1616.5
  Top w39.37: L5011.2@907.48,1240.28 1003.94,1240.28 1050.2,1240.28 1066.81,1240.28 1079.85,1240.28 1134.84,1295.28 1203.74,1364.17 1386.81,1364.17 ; 1354.33,1603.35 1386.81,1570.87 1386.81,1364.17 ; 1355.31,926.18 1386.81,957.68 1386.81,1116.14 1386.81,1364.17
  Power w9.84: v1(956.69,1593.5) 971.46,1608.27 1060.04,1608.27 1083.66,1584.65 1083.66,1252.95 v1(1068.9,1238.19)
  Bottom w7.87: v1(1394.69,1117.13) 1823.82,1117.13 v1(1839.57,1132.87)
VCC5V0_SYS: C126.2 C127.2 C135.1 C136.1 C137.1 C138.1 C139.1 C265.1 C558.1 C559.1 C2606.1 C2607.1 C2608.1 C2609.1 C90480.1 C90483.1 C90484.1 C90789.1 C90790.1 CON1.2 CON1.4 D1.1 D37.2 L12.2 Q9514.2 R148.2 R316.1 R95041.1 R95122.2 R95616.2 TP10.1 U1.1 U26.2 U27.5 U28.4 U2602.12 U2602.13 U2603.5 U90077.4 | length 4884.2
  Top w7.87: D1.1@490.16,425.2 491.14,425.2 v1(491.14,397.64)
  Top w9.84: R95122.2@4876.97,2191.93 4898.62,2213.58 4898.62,2223.43 4935.04,2259.84 4935.04,2302.17 4947.82,2302.17 4949.8,2300.19 U1.1@4949.8,2277.56 4949.8,2293.58 4961.88,2281.5 4975.4,2281.5 4975.4,2242.13 5007.87,2209.65 5007.87,2028.54 5024.61,2011.81 5199.8,2011.81 5235.24,1976.38 L12.2@5235.24,1948.82 5235.24,1923.23 5209.65,1897.64 5166.34,1897.64 5114.17,1897.64 ; 5034.45,1870.08 5070.87,1870.08 ; 5283.46,2149.61 5285.43,2147.64 U27.5@5306.1,2147.64
  Top w11.81: U2602.13@4053.77,975.56 4053.77,1013.41 C2609.1@4060.04,1019.68 ; C2608.1@4060.04,1055.12 C2609.1@4060.04,1019.68 ; U2602.12@4073.45,975.56 4073.45,1005.67 4060.04,1019.08 C2609.1@4060.04,1019.68 ; R95122.2@4876.97,2191.93 4876.97,1866.14 5235.24,1866.14 L12.2@5235.24,1948.82
  Top w15.75: v1(2687.01,1703.74) 2691.93,1708.66 C90790.1@2720.47,1708.66 C90789.1@2752.95,1708.66 2754.43,1708.66 2754.43,1743.11 R95616.2@2755.91,1743.11
  Top w19.68: C2608.1@4060.04,1055.12 4138.78,1055.12 4158.46,1035.43 v2(4158.46,979.33) ; 5166.34,1897.64 5165.35,1898.62 5165.35,2130.91 5187.99,2153.54 C139.1@5255.91,2153.54 5255.91,2149.61 5283.46,2149.61
  Top w31.5: C265.1@803.11,1319.87 805.08,1319.87 U90077.4@805.08,1258.85
  Top w35.43: D37.2@5034.45,3170.28 5034.45,3204.72 ; C127.2@5035.43,3259.84 5035.43,3218.5 5034.45,3217.52 5034.45,3204.72 ; U26.2@5303.15,3183.07 5303.15,3232.28 5284.45,3250.98 5240.16,3250.98 5193.9,3204.72 5034.45,3204.72
  Power w9.84: v2(3946.85,694.88) 3950.83,694.88 4158.46,902.52 v2(4158.46,979.33)
  Bottom w39.37: v2(4971.46,1958.66) 4971.46,2171.75 4828.74,2314.47 4828.74,2674.47 4784.45,2718.76 4784.45,3001.23 4998.76,3215.55 v2(5048.23,3215.55)
  other v1: 244.09,769.68 645.67,2944.88 663.39,2944.88 681.1,2944.88
  other v2: 3925.2,694.88 3925.2,716.54 3946.85,716.54 828.74,1310.04 850.39,1310.04 828.74,1331.69 850.39,1331.69 5036.42,1891.73 5058.07,1891.73 5079.72,1891.73 5014.76,1892.72 5036.42,1913.39 5058.07,1913.39 5079.72,1913.39 4949.8,1914.37 4971.46,1914.37 4993.11,1914.37 5014.76,1914.37 4949.8,1936.02 4971.46,1936.02 5014.76,1936.02 5036.42,1936.02 5058.07,1936.02 5079.72,1936.02 5101.38,1936.02 4993.11,1937.01 5014.76,1957.68 5036.42,1957.68 5058.07,1957.68 5079.72,1957.68 5101.38,1957.68 4949.8,1958.66 4993.11,1958.66 2474.41,2734.25 2496.06,2734.25 2517.72,2734.25 5069.88,3214.57 5061.02,3234.25
VCC5V0_USB: C85.1 C130.1 C131.1 C90582.2 C90773.1 L4.1 R148.1 R91375.1 U90115.5 U90128.5 | length 3114.8
  Top w3.94: v2(4895.67,1718.5) 4883.86,1716.54 4881.89,1716.54 4881.89,1751.97 4908.46,1751.97 4914.86,1758.37 R148.1@4970.96,1758.37
  Top w11.81: R91375.1@1330.71,517.72 1368.11,517.72 1382.87,502.95 U90115.5@1395.67,502.95
  Top w19.68: v2(3118.11,940.94) 3150.59,940.94 v2(3172.24,919.29) ; 3218.5,591.54 3232.28,605.31 U90128.5@3232.28,609.25 ; 3831.69,1073.82 3820.87,1073.82 C85.1@3817.91,1070.87 ; C85.1@3817.91,1070.87 L4.1@3819.88,1104.33 ; C85.1@3817.91,1070.87 v2(3823.82,1049.21) v2(3845.47,1049.21) ; L4.1@3819.88,1104.33 3812.01,1096.46 3812.01,1048.23 v2(3802.17,1048.23) 3802.17,1047.44 3845.47,1047.44 v2(3845.47,1049.21) ; L4.1@3819.88,1104.33 3845.47,1078.74 v2(3845.47,1049.21)
  Top w59.06: v2(3107.28,922.24) 3107.28,647.04 3162.78,591.54 3218.5,591.54
  Bottom w19.68: v2(3823.82,1049.21) v2(3845.47,1049.21)
  Bottom w39.37: v2(1355.31,445.87) 1355.31,525.59 1454.72,625 1997.05,625 2033.46,661.42 2033.46,821.85 2111.22,899.61 3106.3,899.61 v2(3128.94,922.24)
  other v2: 1336.61,435.04 1336.61,456.69 3150.59,922.24 3096.46,940.94 3139.76,940.94 4863.19,1679.13 4884.84,1679.13 4906.5,1679.13 4851.38,1696.85 4873.03,1697.83 4895.67,1697.83 4917.32,1697.83 4917.32,1718.5 4852.36,1719.49 4874.02,1719.49
VCC5V0_USB1: C2282.1 C2283.1 C2284.1 U90115.1 USB2502.1 | length 538.8
  Top w11.81: U90115.1@1505.91,502.95 1505.91,461.61 1523.62,443.9 C2284.1@1523.62,432.09 1552.17,432.09 1560.04,439.96 1560.04,443.9 C2283.1@1562.01,445.87
  Top w19.68: U90115.1@1505.91,502.95 1561.02,502.95 C2282.1@1561.02,499.02
  Top w27.56: C2282.1@1561.02,499.02 1562.01,499.02 C2283.1@1562.01,445.87
  Bottom w39.37: v2(1536.42,451.77) 1565.94,451.77 1693.9,323.82 v2(1693.9,233.27)
  other v2: 1683.07,251.97 1704.72,251.97 1514.76,451.77 1525.59,470.47
VCC12V: C132.1 C133.1 C134.1 C146.1 C147.1 R149.2 R150.1 R158.1 U27.1 U28.1 U29.5 | length 4494.4
  Top w9.84: R158.1@5710.63,2490.16 5710.63,2529.53 5675.2,2564.96 5566.93,2564.96 5544.29,2542.32 5514.76,2542.32 5428.15,2455.71 v2@5425.2,2455.71 ; v2@5425.2,2455.71 5420.28,2460.63 5311.02,2460.63 R150.1@5311.02,2437.99 5294.29,2421.26 5294.29,2292.25 5341.99,2244.55 5341.54,2244.55 C133.1@5341.54,2244.09 5357.28,2228.35 5357.28,2188.98 5382.87,2163.39 U27.1@5382.88,2179.13 5382.87,2154.53 5391.34,2154.53 5397.76,2160.95 5397.64,2161.07 5397.64,2195.6 5406.76,2204.72 5437.99,2204.72 R149.2@5464.57,2231.3 5464.57,2231.76 5464.11,2231.76 5501.05,2268.7 5562.01,2268.7 5638.78,2345.47 5661.42,2345.47 U29.5@5661.42,2354.33 5661.42,2352.89 5654.07,2352.89 5605.38,2401.57 5479.33,2401.57 v2@5425.2,2455.71
  Power w78.74: U28.1@5240.58,294.47 5429.31,294.47 5827.76,692.91 5827.76,1618.11 5938.98,1729.33 5938.98,2280.51 5769.69,2449.8 v2(5451.77,2449.8)
  other v2: 5365.16,2449.8 5386.81,2449.8 5408.46,2449.8 5430.12,2449.8 5365.16,2471.46 5386.81,2471.46 5408.46,2471.46 5430.12,2471.46 5451.77,2471.46
VCC12V_DCIN: C140.1 C142.1 C151.2 C152.1 D45.2 D46.2 D47.2 R150.2 R151.2 TP9.1
VCC_1V8_S0: C90618.2 R2311.1 R90337.1 R95209.1 R95467.1 R95557.1 R95558.1 U33.88 U33.90 U90089.B2 U90089.C2 | length 12724.2
  Top w2.95: 528.55,1502.29 528.55,1516.01
  Top w5.91: U90089.C2@518.71,1529.53 528.55,1519.69 528.55,1516.01 ; 528.55,1502.29 528.55,1468.5 C90618.2@534.45,1468.5
  Top w7.87: U90089.C2@518.71,1529.53 U90089.B2@518.71,1549.21 ; C90618.2@534.45,1468.5 552.17,1450.79 v1(556.1,1450.79) ; v1(610.24,1395.67) 631.89,1374.02 631.89,1099.41 681.1,1050.2 740.16,1050.2 746.06,1056.1 R95209.1@746.06,1075.79 ; U33.88@4415.75,2680.51 4389.37,2680.51 4377.95,2691.93 4377.95,2692.91 4381.3,2696.26 U33.90@4415.75,2696.26 ; v1(5306.1,1728.35) 6062.99,1728.35 6076.77,1742.13 6076.77,1794.29 6071.85,1799.21 R2311.1@6052.17,1799.21
  Top w9.84: R95209.1@746.06,1075.79 775.59,1075.79 810.04,1041.34 v1(810.04,865.16) ; R95467.1@2703.74,2984.25 2722.44,2984.25 2732.28,2994.09 2732.28,3054.68 2872.05,3194.45 v1(2872.05,3198.82) ; R90337.1@4600.39,610.24 4616.14,610.24 v1(4619.09,613.19) 4624.38,618.48 R95558.1@4624.38,633.06
  Top w15.75: v2(4454.72,715.55) 4476.38,715.55 R95557.1@4476.38,714.57
  Top w19.68: 4913.39,2920.28 v2(4953.74,2879.92) ; v2(4972.44,2893.7) 4963.58,2887.17 ; v2(4953.74,2879.92) 4963.58,2887.17 ; v2(4953.74,2879.92) v2(4973.43,2872.05) 4973.43,2877.33 4963.58,2887.17
  Top w27.56: 4377.95,2692.91 4354.08,2692.91 4340.55,2706.44 4340.55,2861.22 4399.61,2920.28 4913.39,2920.28 4945.87,2920.28 v2(4972.44,2893.7)
  Power w11.81: v1(2872.05,3198.82) 2872.05,3120.08 2953.74,3038.39 3447.83,3038.39 3517.72,2968.5 4897.64,2968.5 v2(4972.44,2893.7)
  Bottom w7.87: v1(556.1,1450.79) 556.1,1449.8 v1(610.24,1395.67)
  Bottom w11.81: v1(810.04,865.16) 1200.79,865.16 1262.8,803.15 1492.13,803.15 1687.99,999.02 3030.51,999.02 3052.17,1020.67 3187.99,1020.67 3429.13,779.53 3779.53,779.53 3812.01,812.01 3812.01,867.07 3857.34,912.4 3877.95,912.4 3894.69,895.67 4058.8,895.67 4238.92,715.55 v2(4454.72,715.55)
  Bottom w19.68: v2(4454.72,715.55) 4515.75,654.53 4597.44,654.53 4619.09,632.87 ; v2(4972.44,2893.7) v2(4953.74,2879.92) v2(4973.43,2872.05) 4978.63,2872.05 4998.03,2891.45 4998.03,2893.7 ; v1(5306.1,1728.35) 5305.12,1706.69 5305.12,1219.49 5047.24,961.61 4887.8,961.61 4807.09,880.91 4787.4,880.91 4737.2,830.71 4737.2,642.72 4707.68,613.19 4638.78,613.19 ; 4619.09,632.87 v1(4619.09,613.19) 4638.78,613.19 ; 4619.09,632.87 4638.78,613.19
  Bottom w27.56: v2(4972.44,2893.7) 4998.03,2893.7 5040.35,2893.7 5188.98,2745.08 5188.98,1859.25 5306.1,1742.13 v1(5306.1,1728.35)
VCC_1V8_S3: C90782.2 C90783.2 C90784.2 C90788.2 R4203.2 R95589.2 U90132.B2 U90132.C2 U90133.B2 U90133.C2 U90135.B2 U90135.C2 U90136.B2 U90136.C2 | length 9753.5
  Top w2.95: 691.93,1514.62 691.93,1525.67 ; 812.99,1513.16 812.99,1527.82 ; 966.54,1512.59 966.54,1525.85 ; 1332.43,2392.36 1332.43,2410.01
  Top w3.94: U90133.C2@682.09,1541.34 691.93,1531.5 691.93,1525.67
  Top w5.91: 691.93,1514.62 691.93,1490.15 C90783.2@698.82,1483.27 ; U90132.C2@803.15,1541.34 812.99,1531.5 812.99,1527.82 ; 812.99,1513.16 812.99,1489.17 C90782.2@818.9,1483.27 ; U90135.C2@956.7,1539.37 966.54,1529.53 966.54,1525.85 ; 966.54,1512.59 966.54,1486.22 C90784.2@970.47,1482.28
  Top w7.87: U90133.C2@682.09,1541.34 U90133.B2@682.09,1561.02 ; U90132.C2@803.15,1541.34 U90132.B2@803.15,1561.02 ; U90135.C2@956.7,1539.37 U90135.B2@956.7,1559.05 ; C90788.2@1327.12,2440.33 1332.43,2435.01 1332.43,2410.01 ; 1332.43,2392.36 1342.27,2382.52 U90136.C2@1342.27,2382.45 U90136.B2@1342.27,2362.77 ; v1(4669.29,3122.05) R4203.2@4710.63,3122.05
  Top w9.84: v1(693.9,1452.76) 693.9,1483.27 C90783.2@698.82,1483.27 ; v1(818.9,1445.87) C90782.2@818.9,1483.27 ; C90784.2@970.47,1482.28 972.44,1482.28 v1(972.44,1445.87)
  Top w11.81: v1(120.08,1465.55) 302.17,1465.55 398.62,1369.09 553.9,1369.09 637.56,1452.76 v1(693.9,1452.76) ; v1(176.46,2653.33) 221.12,2653.33 352.81,2521.64 1245.8,2521.64 C90788.2@1327.12,2440.33 ; v1(4710.63,3274.61) 4733.27,3274.61 R95589.2@4733.27,3275.59
  Power w7.87: v1(4669.29,3122.05) 4669.29,3213.58 4710.63,3254.92 v1(4710.63,3274.61)
  Power w9.84: v1(693.9,1452.76) 700.79,1445.87 v1(818.9,1445.87) v1(972.44,1445.87)
  Power w11.81: v1(120.08,1465.55) 91.54,1494.09 91.54,2640.13 84.65,2647.02 ; v1(176.46,2653.33) 97.51,2653.33 ; v1(4710.63,3274.61) 4646.65,3274.61 4372.05,3000 3531.5,3000 3465.55,3065.94 2964.57,3065.94 2908.46,3122.05 2908.46,3207.68 2759.84,3356.3 2316.93,3356.3 2256.89,3296.26 113.19,3296.26 84.65,3267.72 84.65,2666.19 ; 84.65,2647.02 90.95,2653.33 97.51,2653.33 ; 84.65,2647.02 84.65,2666.19 ; 84.65,2666.19 97.51,2653.33
VCC_3V3_S0: C573.1 C574.1 C2332.1 L3.2 R91.1 R94.1 R96.1 R105.1 R106.1 R95607.2 U2305.1 U90129.22 | length 4680.2
  Top w9.06: U90129.22@4736.4,808.69 4755.7,808.69 4784.63,837.62 C573.1@4784.63,846.09
  Top w11.81: C573.1@4784.63,846.09 C574.1@4784.63,880.54
  Top w13.78: v1(4779.53,828.74) v1(4796.26,828.74) 4796.94,829.2 4785.6,846.09 C573.1@4784.63,846.09
  Top w15.75: R96.1@3519.69,1068.9 R91.1@3597.44,1068.9 L3.2@3633.86,1068.9 3633.86,1136.81 3673.23,1176.18 3846.46,1176.18 3872.05,1150.59 R105.1@3872.05,1021.65 ; v1(3859.25,880.91) 3837.79,880.91 R106.1@3837.79,881.2 3858.27,881.2 3872.05,894.98 R94.1@3872.05,988.19 ; R94.1@3870.08,986.22 R94.1@3872.05,988.19 ; R105.1@3870.08,1021.65 R105.1@3872.05,1021.65 ; R94.1@3872.05,988.19 R105.1@3872.05,1021.65
  Top w19.68: 5676.18,1868.11 5676.18,1873.03 ; U2305.1@5791.34,1864.17 5803.15,1864.17 5803.15,1892.72 5676.18,1892.72 5676.18,1873.03 ; 5802.89,1892.57 5786.02,1909.45 v2(5734.25,1909.45) v2(5712.6,1909.45) 5676.18,1873.03
  Top w23.62: 5676.18,1868.11 5676.18,1864.17 U2305.1@5791.34,1864.17
  Bottom w9.84: v1(3870.08,894.68) 3893.7,871.06
  Bottom w11.81: v1(3859.25,880.91) 3843.5,865.16 3863.19,865.16 3869.09,871.06
  Bottom w15.75: v1(3859.25,880.91) v1(3870.08,894.68) ; v1(4796.26,828.74) v1(4779.53,828.74) ; 4797.24,811.02 v1(4779.53,828.74) ; 4815.94,847.44 4798.23,847.44 v1(4779.53,828.74)
  Bottom w19.68: v2(5701.77,1889.76) v2(5712.6,1909.45) v2(5734.25,1909.45) v2(5723.43,1889.76) v2(5701.77,1889.76)
  Bottom w27.56: v1(3859.25,880.91) 3869.09,871.06 ; 3893.7,871.06 4049.21,871.06 4374.02,546.26 4746.06,546.26 4797.24,597.44 4797.24,800.2 v1(4796.26,828.74) ; 4797.24,811.02 v1@4797.24,828.74
  Bottom w31.5: v1(4796.26,828.74) 4797.24,828.74 4815.94,847.44 4900.59,932.09 5060.04,932.09 5320.87,1192.91 5615.16,1192.91 5723.43,1301.18 v2(5723.43,1889.76)
VCC_3V3_S3: C2330.1 C2614.1 C90787.2 D90038.1 Q1.2 R12.1 R220.1 R2613.1 R9241.1 R95572.1 R95590.1 R95591.1 R95592.1 R95593.1 R95607.1 U33.84 U33.86 U2305.5 U2602.3 U2602.4 U90089.A2 U90132.A2 U90133.A2 U90136.A2 | length 16039.4
  Top w3.94: 4838.58,2957.68 4838.58,2972.44 R9241.1@4840.55,2972.44
  Top w7.87: v1(182.7,2626.59) 225.58,2626.59 346.27,2505.91 1242.05,2505.91 1260.83,2487.13 v1(1260.83,2473.43) ; U90089.A2@518.71,1568.9 v1(518.7,1581.69) ; U90133.A2@682.09,1580.71 v1(682.09,1594.49) ; U90132.A2@803.15,1580.71 v1(803.15,1602.36) ; C90787.2@803.15,1622.05 C90787.2@806.1,1622.05 ; U90136.A2@1342.27,2343.08 1342.27,2325.05 v1(1342.52,2324.8) ; U33.84@4415.75,2649.02 4379.53,2649.02 4373.03,2655.51 4382.28,2664.76 U33.86@4415.75,2664.76 ; R12.1@5321.85,1221.46 5323.63,1221.46 Q1.2@5323.63,1178.86
  Top w9.84: v1(5674.21,2514.76) 5673.67,2514.76 5675.2,2512.8 R95572.1@5675.2,2490.16
  Top w11.81: v1(318.9,2761.81) 365.16,2761.81 D90038.1@379.92,2776.57 ; v1(803.15,1602.36) C90787.2@803.15,1622.05 ; U2602.3@4015.97,908.24 3983.04,908.24 C2614.1@3978.35,903.54 3980.79,903.54 4000.98,883.35 4000.98,853.73 R2613.1@4017.35,837.37 4034.08,854.1 U2602.4@4034.08,880.28
  Top w15.75: v2(3995.08,828.74) 4008.72,828.74 R2613.1@4017.35,837.37
  Top w19.68: v2(169.29,1550.2) 201.77,1550.2 221.46,1569.88 v2(222.44,1569.88) ; v2(1180.12,1642.72) 1271.65,1734.25 1655.51,1734.25 1729.33,1660.43 R95591.1@1854.33,1660.43 R95590.1@1890.75,1660.43 R95593.1@1928.15,1660.43 R95592.1@1964.57,1660.43 ; 4763.78,2957.68 4764.76,2957.68
  Top w31.5: U2305.5@5901.58,1864.17 5961.61,1864.17 C2330.1@5961.61,1856.3
  Top w39.37: 4373.03,2655.51 4338.58,2655.51 4303.15,2690.94 4303.15,2876.71 4384.11,2957.68 4763.78,2957.68 ; 4764.76,2957.68 4838.58,2957.68 5044.29,2957.68 v2(5094.49,2907.48)
  Bottom w7.87: v1(1260.83,2473.43) 1260.83,2346.46 1282.48,2324.8 v1(1342.52,2324.8)
  Bottom w11.81: v2(169.29,1550.2) 170.28,1551.18 111.22,1610.24 111.22,2555.12 v1(182.7,2626.59) 318.41,2762.3 v1(318.9,2761.81) ; v1(5674.21,2514.76) 5688.6,2529.15 5691.93,2525.82
  Bottom w15.75: v2(169.29,1550.2) 89.57,1470.47 89.57,837.6 106.3,820.87 1190.94,820.87 1242.13,769.68 1506.89,769.68 1699.8,962.6 3042.89,962.6 3067.49,987.2 3169.74,987.2 3410.88,746.06 3826.77,746.06 3901.57,820.87 3987.2,820.87 v2(3995.08,828.74)
  Bottom w19.68: v2(222.44,1569.88) 234.25,1581.69 v1(518.7,1581.69) 531.5,1594.49 v1(682.09,1594.49) 795.28,1594.49 v1(803.15,1602.36) 843.5,1642.72 v2(1180.12,1642.72)
  Bottom w23.62: v2(3995.08,828.74) 4039.37,828.74 4351.38,516.73 4758.29,516.73 4826.77,585.21 4826.77,813.73 4912.65,899.61 5112.2,899.61 ; v2(5993.11,1846.46) 6030.51,1846.46
  Bottom w39.37: v2(5094.49,2907.48) 5310.27,2907.48 5688.6,2529.15 ; 5112.2,899.61 5354.33,1141.73 5872.05,1141.73 6043.31,1312.99 6043.31,1833.66 6030.51,1846.46 ; 5691.93,2525.82 5766.73,2451.01 5766.73,1993.11 5870.08,1889.76 v2(5992.13,1889.76)
  other v1: 5360.24,1135.83 5342.52,1139.76 5353.35,1153.54
  other v2: 6014.76,1846.46 5993.11,1868.11 6014.76,1868.11 6013.78,1889.76 5101.57,2887.4 5115.35,2903.54
VCC_LDO5V: P4.1 R155.1 | length 40.4
  Top w9.84: P4.1@5192.91,2086.61 5230.31,2086.61 R155.1@5230.31,2083.66
VCC_LEDA: C90409.1 D5000.2 U90082.5 U90104.38 U90104.39 | length 1008.9
  Top w9.84: v2(2135.83,2789.37) 2135.83,2759.84 C90409.1@2141.73,2759.84 ; U90104.39@2326.77,3336.61 2326.77,3261.81 2338.58,3250 U90104.38@2338.58,3223.43 v1(2338.58,3186.02)
  Top w15.75: v1(2338.58,3168.31) v1(2338.58,3186.02)
  Top w23.62: C90409.1@2141.73,2759.84 2150.59,2768.7 U90082.5@2150.59,2834.65 2150.59,2866.14 2162.4,2877.95 2228.35,2877.95 2260.82,2845.48 D5000.2@2260.82,2813.97
  Power w19.68: v1(2338.58,3168.31) v1(2338.58,3186.02)
  Power w23.62: v2(2135.83,2789.37) v2(2157.48,2789.37)
  Power w27.56: v2(2157.48,2789.37) 2220.47,2789.37 2338.58,2907.48 v1(2338.58,3168.31)
VCC_LEDK: R5004.1 R95071.2 U90104.34 U90104.35 | length 628.7
  Top w9.84: U90104.35@2374.02,3336.61 2374.02,3289.37 2385.83,3277.56 U90104.34@2385.83,3223.43
  Top w15.75: R95071.2@2065.94,2973.43 2079.02,2973.43 2130.2,3024.61 2120.64,3024.61 R5004.1@2125,3024.61 2125,3028.54 2174.21,3077.76 2352.36,3077.76 2385.83,3111.22 U90104.34@2385.83,3223.43
VCC_MIPI: C34.1 C90431.1 FB6.2 J6.1 J6.2 | length 473.3
  Top w19.68: FB6.2@1949.8,3015.75 C90431.1@1992.13,3015.75 ; J6.2@2019.69,3192.91 2019.69,3022.64 2012.8,3015.75 C90431.1@1992.13,3015.75 ; J6.1@2059.06,3192.91 2059.06,3042.32 C34.1@2035.43,3018.7 1992.13,3018.7 C90431.1@1992.13,3015.75
VCC_RTC: D2.2 D90038.2 R95373.1 | length 125.6
  Top w11.81: D90038.2@474.41,2776.57 D2.2@474.41,2714.92 508.23,2714.92 R95373.1@529.53,2736.22
VCC_SYSIN: C90478.1 C90479.1 C90481.2 C90485.1 C90486.1 C90488.1 C90490.1 L5002.2 R95120.1 R95603.1 U1.5 U33.77 U33.79 U33.81 U33.83 U33.85 U33.87 | length 11857.6
  Top w7.87: R95603.1@1250,121.06 1251.97,121.06 v1(1251.97,140.75) ; U33.77@4520.47,2601.77 4798.23,2601.77 4858.27,2661.81 C90485.1@4858.27,2711.61 ; U33.79@4520.47,2617.52 4764.17,2617.52 C90485.1@4858.27,2711.61 ; U33.81@4520.47,2633.27 4767.72,2633.27 4846.06,2711.61 C90485.1@4858.27,2711.61 ; U33.83@4520.47,2649.02 4758.86,2649.02 4804.13,2694.29 4804.13,2712.99 ; U33.85@4520.47,2664.76 4755.91,2664.76 4804.13,2712.99 ; U33.87@4520.47,2680.51 4551.18,2680.51 ; 4732.87,2633.27 4815.94,2550.2 4937.01,2550.2 4960.63,2573.82 L5002.2@4984.25,2573.82 5007.87,2550.2 5086.61,2550.2 5086.61,2742.13 4612.8,2742.13 4551.18,2680.51 ; 4551.18,2680.51 4734.25,2680.51 4793.9,2740.16 C90488.1@4804.13,2740.16 4804.13,2712.99
  Top w9.84: C90488.1@4804.13,2740.16 4753.54,2689.57 4753.54,2321.26 4780.51,2294.29 C90481.2@4807.09,2294.29 4825.79,2294.29 R95120.1@4830.71,2289.37 ; U1.5@5026.58,2309.05 5058.07,2309.05 C90486.1@5061.02,2306.1
  Top w19.68: C90486.1@5061.02,2306.1 5107.28,2306.1 5123.03,2321.85 5123.03,2658.46 5069.88,2711.61 C90490.1@5062.01,2711.61
  Power w7.87: v1(1251.97,140.75) 1272.64,120.08 2322.83,120.08 2482.28,-39.37 3450.79,-39.37 3787.4,297.24 v1(3816.93,297.24) ; v1(5074.8,2684.06) 5359.25,2399.61 5751.97,2399.61 5891.73,2259.84 5891.73,1748.9 5780.51,1637.68 5780.51,712.48 5429.25,361.22 v1(5380.91,361.22)
  Bottom w7.87: v1(3816.93,297.24) 3937.99,297.24 4002.95,362.2 5379.92,362.2 v1(5380.91,361.22)
VCCIO_FLASH: R95374.2 R95375.1 R95589.1 U33.73 | length 7212.4
  Top w4.92: v1(294.29,2782.48) 331.69,2782.48 455.71,2906.5 503.94,2906.5 508.86,2901.57 ; 514.76,2895.67 508.86,2901.57 ; 520.67,2901.57 508.86,2901.57
  Top w5.91: R95374.2@514.76,2859.25 514.76,2895.67 520.67,2901.57 535.43,2916.34 902.56,2916.34 R95375.1@923.23,2895.67
  Top w7.87: 4489.17,2571.85 4492.13,2570.28 U33.73@4520.47,2570.28
  Top w9.84: v1(4715.55,3220.47) 4733.27,3238.19 R95589.1@4733.27,3244.09
  Top w11.81: 4489.17,2571.85 4475.39,2585.63 4475.39,2640.75 4456.69,2659.45 4456.69,2828.74 4502.95,2875 v1(4716.54,2875)
  Power w5.91: v1(294.29,2782.48) 193.9,2782.48 97.44,2878.94 97.44,3262.42 118.49,3283.46 2262.19,3283.46 2322.23,3343.5 2752.99,3343.5 2886.81,3209.69 2886.81,3125.61 2961.24,3051.18 3453.13,3051.18 3520.06,2984.25 4690.94,2984.25 4704.72,2998.03 v1(4704.72,3028.54)
  Power w15.75: v1(4704.72,3028.54) 4704.72,3209.65 v1(4715.55,3220.47)
  Bottom w11.81: v1(4704.72,3028.54) 4707.68,3025.59 4707.68,2883.86 v1(4716.54,2875)
VD33: C83.2 L3.1 U17.20 | length 133.7
  Top w9.84: U17.20@3674.4,957.97 3674.4,981.11 ; C83.2@3674.4,1037.59 C83.2@3677.17,1040.35
  Top w15.75: L3.1@3633.86,1037.4 3677.17,1037.4 C83.2@3677.17,1040.35 3674.4,1037.59 3674.4,981.11
WIFI_HOST_WAKE: R95613.1 U4301.21 | length 4679.6
  Top w3.94: v1(1500,1008.86) 1500,1124.02 1487.2,1136.81 1487.2,1363.98 1552.72,1429.49 U4301.21@1589.78,1429.49
  Top w7.87: v1(5193.9,1293.31) 5217.52,1293.31 R95613.1@5255.41,1255.41
  Bottom w3.94: v1(1500,1008.86) 1521.65,1008.86 1533.46,1020.67 2026.57,1020.67 2029.53,1017.72 2591.54,1017.72 2646.65,1072.83 3872.72,1072.83 3936.7,1008.86 4537.4,1008.86 4545.28,1000.98 4545.28,875.2 4562.21,858.27 4590.35,858.27 4649.09,917 4649.09,996.58 4945.81,1293.31 v1(5193.9,1293.31)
